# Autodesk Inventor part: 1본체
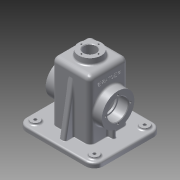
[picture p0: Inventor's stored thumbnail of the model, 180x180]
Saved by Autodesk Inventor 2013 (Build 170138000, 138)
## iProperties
Created: 2016-01
Part Number: 1본체
Material: 알루미늄 6061
Document SubType Name: Modeling
Designer: Administrator
Density: 2.71 g/cm^3
Mass: 810.011 g
Surface Area: 906.161 cm^2
Volume: 298.897 cm^3
Author: Administrator
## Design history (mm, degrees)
sketch "스케치1"
  geometry: L1 (-65, 57.5)-(65, 57.5); L2 (65, 57.5)-(65, -57.5); L3 (65, -57.5)-(-65, -57.5); L4 (-65, -57.5)-(-65, 57.5); 3 further points
  constraints: 8 end point, 2 midpoint, 2 parallel, 1 horizontal, 1 horizontal alignment, 1 perpendicular, 1 vertical alignment
  dimensions: "d0" = 130 distance of L1.start L1.end; "d2" = 115 distance of L1.end L2.end
extrude "돌출1" new body sketch "스케치1" distance "d3" = 8; taper "d4" = 0 deg
sketch "스케치2"
  geometry: L1 (-60, -52.5)-(60, -52.5); L2 (60, -52.5)-(60, 52.5); L3 (60, 52.5)-(-60, 52.5); L4 (-60, 52.5)-(-60, -52.5); 3 further points
  constraints: 8 end point, 2 midpoint, 2 parallel, 1 horizontal, 1 horizontal alignment, 1 perpendicular, 1 vertical alignment
  dimensions: "d5" = 120 distance of L1.start L1.end; "d7" = 105 distance of L3.end L1.start
extrude "돌출2" join sketch "스케치2" distance "d8" = 2; taper "d9" = 0 deg
fillet "모깎기1" dims "d10" = 10
fillet "모깎기2" dims "d11" = 15
sketch "스케치3"
  geometry: C1 r 7.5 at (-50, 42.5); C2 r 7.5 at (-50, -42.5); C3 r 7.5 at (50, -42.5); C4 r 7.5 at (50, 42.5); A1 r 15 centre (-50, -42.5) between (-65, -42.5) and (-50, -57.5) reference; A2 r 15 centre (50, -42.5) between (50, -57.5) and (65, -42.5) reference; A3 r 15 centre (50, 42.5) between (65, 42.5) and (50, 57.5) reference; A4 r 15 centre (-50, 42.5) between (-50, 57.5) and (-65, 42.5) reference; 1 further point
  constraints: 4 centre point, 4 coincident
  dimensions: "d12" = 15 diameter of C1; "d13" = 15 diameter of C2; "d14" = 15 diameter of C3; "d15" = 15 diameter of C4
extrude "돌출3" join sketch "스케치3" distance "d16" = 3; taper "d17" = 0 deg
hole "구멍1" diameter "d20" = 5; stored, may be unused: countersink angle "d24" = 90 deg, drill point angle "d26" = 118 deg; dims "d18" = 10, "d19" = 10, "d21" = 6, "d22" = 4, "d23" = 2, "d25" = 8
hole "구멍2" diameter "d29" = 5; stored, may be unused: countersink angle "d33" = 90 deg, drill point angle "d35" = 118 deg; dims "d27" = 10, "d28" = 10, "d30" = 6, "d31" = 4, "d32" = 2, "d34" = 8
hole "구멍3" diameter "d38" = 5; stored, may be unused: countersink angle "d42" = 90 deg, drill point angle "d44" = 118 deg; dims "d36" = 10, "d37" = 10, "d39" = 6, "d40" = 4, "d41" = 2, "d43" = 8
hole "구멍4" diameter "d47" = 5; stored, may be unused: countersink angle "d51" = 90 deg, drill point angle "d53" = 118 deg; dims "d45" = 10, "d46" = 10, "d48" = 6, "d49" = 4, "d50" = 2, "d52" = 8
sketch "스케치4"
  geometry: L1 (-32.5, 32.5)-(32.5, 32.5); L2 (32.5, 32.5)-(32.5, -32.5); L3 (32.5, -32.5)-(-32.5, -32.5); L4 (-32.5, -32.5)-(-32.5, 32.5); 3 further points
  constraints: 8 end point, 2 midpoint, 2 parallel, 1 horizontal, 1 horizontal alignment, 1 perpendicular, 1 vertical alignment
  dimensions: "d54" = 65 distance of L1.start L1.end; "d56" = 65 distance of L1.end L2.end
extrude "돌출4" join sketch "스케치4" distance "d57" = 100; taper "d58" = 0 deg
sketch "스케치9"
  geometry: L1 (52.5, -2)-(-52.5, -2) reference; L2 (-52.5, -2)-(-52.5, 0) reference; L3 (-52.5, 0)-(-57.5, 0) reference; L4 (-57.5, 0)-(-57.5, 8) reference; L5 (-57.5, 8)-(-32.5, 8) reference; L6 (-32.5, 8)-(-32.5, 108) reference; L7 (-32.5, 108)-(32.5, 108) reference; L8 (32.5, 108)-(32.5, 8) reference; L9 (32.5, 8)-(57.5, 8) reference; L10 (57.5, 8)-(57.5, 0) reference; L11 (57.5, 0)-(52.5, 0) reference; L12 (52.5, 0)-(52.5, -2) reference; L13 (-42.5, -2)-(42.5, -2) reference; L14 (-27.5, 103)-(27.5, 103); L15 (27.5, 103)-(27.5, -2); L16 (27.5, -2)-(-27.5, -2); L17 (-27.5, -2)-(-27.5, 103); 1 further point
  constraints: 8 end point, 2 parallel, 1 horizontal, 1 perpendicular, 1 point on line
  dimensions: "d78" = 5 distance between parallel lines of L8 L15; "d79" = 5 distance between parallel lines of L6 L17; "d80" = 5 distance between parallel lines of L7 L14
extrude "돌출8" cut sketch "스케치9" stored distance "d81" = 55; taper "d82" = 0 deg
sketch "스케치6"
  geometry: L1 (10, 85)-(10, 75) reference; L2 (0, -10)-(0, 75) reference; C1 r 27.5 at (-45, 32.5); 2 further points
  constraints: 1 centre point, 1 horizontal alignment, 1 midpoint
  dimensions: "d63" = 55 diameter of C1; "d65" = 55 distance from line of C1.centre L1
extrude "돌출5" join sketch "스케치6" distance "d66" = 15; taper "d67" = 0 deg
sketch "스케치7"
  geometry: C1 r 20 at (0, 0); 1 further point
  constraints: 1 centre point, 1 coincident
  dimensions: "d68" = 40 diameter of C1
extrude "돌출6" join sketch "스케치7" distance "d69" = 10; taper "d70" = -5 deg
sketch "스케치8"
  geometry: L1 (-47.5, 8)-(-30.996, 101.599); L2 (-30.996, 101.599)-(-30.996, 8); L3 (-57.5, 0)-(-57.5, 8) reference; L4 (-30.996, 8)-(-47.5, 8); L5 (-57.5, 8)-(-42.5, 8) reference; 1 further point
  constraints: 6 end point, 1 point on line, 1 vertical
  dimensions: "d71" = 10 deg angle of L3 L1; "d73" = 10 distance of L3.end L1.start; "d74" = 16.50407 distance of L2.end L1.start; "d75" = 93.59922 distance of L1.end L2.end
extrude "돌출7" join sketch "스케치8" stored distance "d76" = 10; taper "d77" = 0 deg
hole "구멍5" diameter "d85" = 21; stored, may be unused: countersink angle "d89" = 90 deg, drill point angle "d91" = 118 deg; dims "d83" = 10, "d84" = 10, "d86" = 6, "d87" = 4, "d88" = 2, "d90" = 8
hole "구멍6" diameter "d94" = 30; stored, may be unused: countersink angle "d98" = 90 deg, drill point angle "d100" = 0 deg; dims "d92" = 10, "d93" = 10, "d95" = 6, "d96" = 35, "d97" = 17, "d99" = 8
hole "구멍7" diameter "d103" = 30; stored, may be unused: countersink angle "d107" = 90 deg, drill point angle "d109" = 0 deg; dims "d101" = 10, "d102" = 10, "d104" = 6, "d105" = 35, "d106" = 17, "d108" = 8
sketch "스케치10"
  geometry: C1 r 10.5 at (0, 0) reference; 1 further point
  constraints: 1 horizontal alignment
  dimensions: "d110" = 14.5 distance of point (14.5, 0) C1.centre
hole "구멍8" sketch "스케치10" at (14.5, 0) diameter "d111" = 2.459; stored, may be unused: countersink angle "d115" = 90 deg, drill point angle "d117" = 118 deg; dims "d112" = 7, "d113" = 35, "d114" = 17, "d116" = 9
sketch "스케치11"
  geometry: C1 r 17.5 at (0, 0) reference; 2 further points
  constraints: 1 horizontal alignment
  dimensions: "d121" = 21 distance of point (21, 0) C1.centre
hole "구멍9" sketch "스케치11" at (21, 0) diameter "d122" = 3.242; stored, may be unused: countersink angle "d126" = 90 deg, drill point angle "d128" = 118 deg; dims "d123" = 8, "d124" = 35, "d125" = 17, "d127" = 10
sketch "스케치12"
  geometry: L1 (27.5, 103)-(27.5, -2) reference; L2 (32.5, 8)-(32.5, 108) reference; L3 (42.5, 8)-(32.5, 8); L4 (32.5, 8)-(32.5, 27.958); L5 (32.5, 27.958)-(42.5, 27.958); L6 (42.5, 27.958)-(42.5, 8); L7 (-50, 8)-(50, 8) reference; 1 further point
  constraints: 8 end point, 2 parallel, 1 collinear, 1 horizontal, 1 perpendicular, 1 point on line
  dimensions: "d136" = 15 distance between parallel lines of L6 L1; "d137" = 19.95823 distance of L5.end L3.start
extrude "돌출9" join sketch "스케치12" stored distance "d134" = 6; taper "d135" = 0 deg
fillet "모깎기5" dims "d138" = 8
fillet "모깎기6" dims "d139" = 8
fillet "모깎기7" dims "d140" = 3
fillet "모깎기8" dims "d141" = 3
fillet "모깎기9" dims "d142" = 1
fillet "모깎기10" dims "d143" = 3
fillet "모깎기11" dims "d144" = 3
fillet "모깎기12" dims "d145" = 3
fillet "모깎기13" dims "d146" = 0.3
sketch "스케치14"
  geometry: L1 (-18, 5.375)-(-18, 43.625) reference; A1 r 30.5 centre (47, 24.5) between (28.834, 49) and (28.834, 0) reference; 2 further points
  constraints: 1 horizontal alignment, 1 other
  dimensions: "d148" = 27 distance from line of L1 point (9, 24.5)
feature "엠보싱1" sketch "스케치14" dims "d149" = 0.5, "d150" = 0
fillet "모깎기14" dims "d151" = 3
chamfer "모따기1" distance "d152" = 1; stored, may be unused: second distance "d153" = 2, angle "d154" = 45 deg
node "솔리드1"
mirror "대칭1"
mirror "대칭2"
pattern_circular "원형 패턴1" dims angle "d119" = 360 deg
pattern_circular "원형 패턴2" dims angle "d130" = 360 deg
mirror "대칭3"
mirror "대칭4"
node "절단 모서리 투영1"
